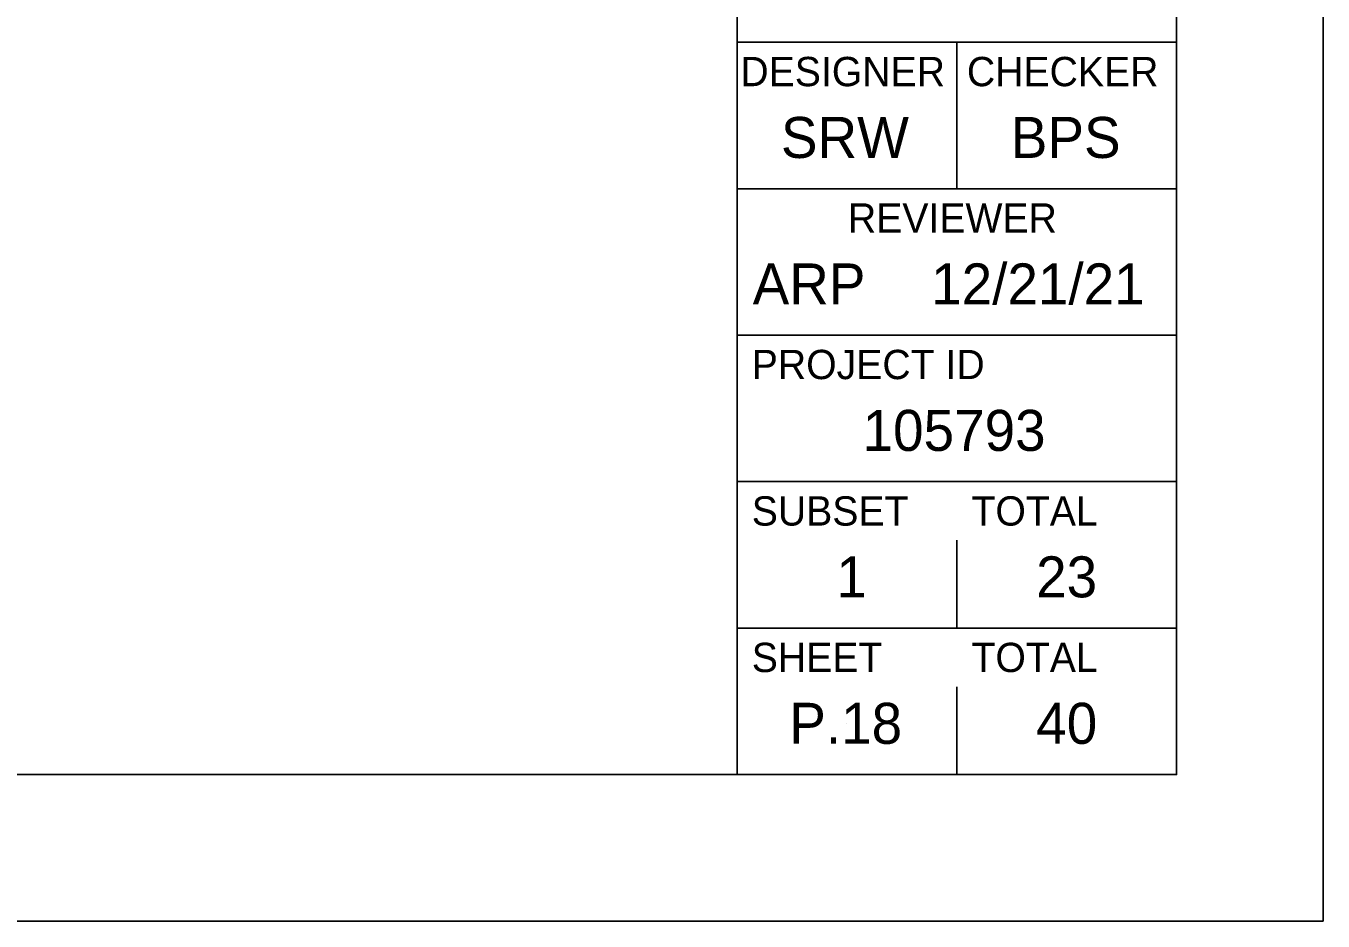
# Model space of a CAD drawing. Extents: x 58.8 to 101.8, y -10 to 13.1.
# Drawn here: x 88.36 to 92.787, y -8.862 to -5.806 of the extents above; entities that cross this region are included whole.
import ezdxf

# ---------------------------------------------------------------- set-up
doc = ezdxf.new("R2010")
doc.units = 0
for name, color, linetype in [('DT_X_Contour_Major', 7, 'Continuous'), ('DT_X_Contour_Minor', 7, 'Continuous'), ('DT_X_Spot_Elev', 7, 'Continuous')]:
    doc.layers.add(name, color=color, linetype=linetype)

msp = doc.modelspace()

# ---------------------------------------------------------------- linework, layer by layer
at = {"layer": 'DT_X_Contour_Major'}
for p, q in [((91.5372, -7.8619), (91.5372, -7.5619)), ((91.5372, -8.3619), (91.5372, -8.0619)), ((91.1622, -8.1869), (91.1622, -8.1869))]:
    msp.add_line(p, q, dxfattribs=at)
msp.add_lwpolyline([(83.5373, -1.8644), (90.7872, -1.8644), (90.7872, -8.3619), (83.5373, -8.3619)], close=True, dxfattribs=at)
at = {"layer": 'DT_X_Contour_Minor'}
msp.add_lwpolyline([(58.7872, -8.8619), (92.7872, -8.8619), (92.7872, 13.1381), (58.7872, 13.1381)], close=True, dxfattribs=at)
at = {"layer": 'DT_X_Spot_Elev'}
for p, q in [((90.7872, -8.3619), (90.7872, 12.6381)), ((90.7872, -5.8619), (92.2872, -5.8619)), ((91.5372, -5.8619), (91.5372, -6.3619)), ((90.7872, -6.3619), (92.2872, -6.3619)), ((90.7872, -6.8619), (92.2872, -6.8619)), ((90.7872, -7.3619), (92.2872, -7.3619)), ((90.7872, -7.8619), (92.2872, -7.8619))]:
    msp.add_line(p, q, dxfattribs=at)
msp.add_lwpolyline([(60.2872, 12.6381), (92.2872, 12.6381), (92.2872, -8.3619), (60.2872, -8.3619)], close=True, dxfattribs=at)

# ---------------------------------------------------------------- texts
at = {"layer": 'DT_X_Contour_Major'}
for s, height, p in [('DESIGNER', 0.1, (90.7983, -6.0119)), ('CHECKER', 0.1, (91.5715, -6.0119)), ('SRW', 0.14, (90.9369, -6.2569)), ('BPS', 0.14, (91.7216, -6.2569)), ('REVIEWER', 0.1, (91.1655, -6.5119)), ('ARP', 0.14, (90.8404, -6.7569)), ('12/21/21', 0.14, (91.4497, -6.7569)), ('PROJECT ID', 0.1, (90.8372, -7.0119)), ('105793', 0.14, (91.2155, -7.2569)), ('SUBSET', 0.1, (90.8372, -7.5119)), ('TOTAL', 0.1, (91.5872, -7.5119)), ('23', 0.14, (91.8079, -7.7569)), ('1', 0.14, (91.1259, -7.7569)), ('SHEET', 0.1, (90.8372, -8.0119)), ('TOTAL', 0.1, (91.5872, -8.0119)), ('P.18', 0.14, (90.9654, -8.2569)), ('40', 0.14, (91.8082, -8.2569))]:
    msp.add_text(s, height=height, dxfattribs=at).set_placement(p)

doc.saveas('drawing.dxf')
